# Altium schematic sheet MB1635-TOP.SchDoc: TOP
size A3; Date: Not used; ApprovedBy: Not used; CheckedBy: Not used; Author: Not used; CompanyName: STMicroelectronics; DrawnBy: Not used; Engineer: Not used; Organization: Not used; Address1: Not used; Address2: Not used; Address3: Not used; Address4: Not used; DocumentNumber: 2; Revision: Not used; SheetNumber: 2; SheetTotal: 17
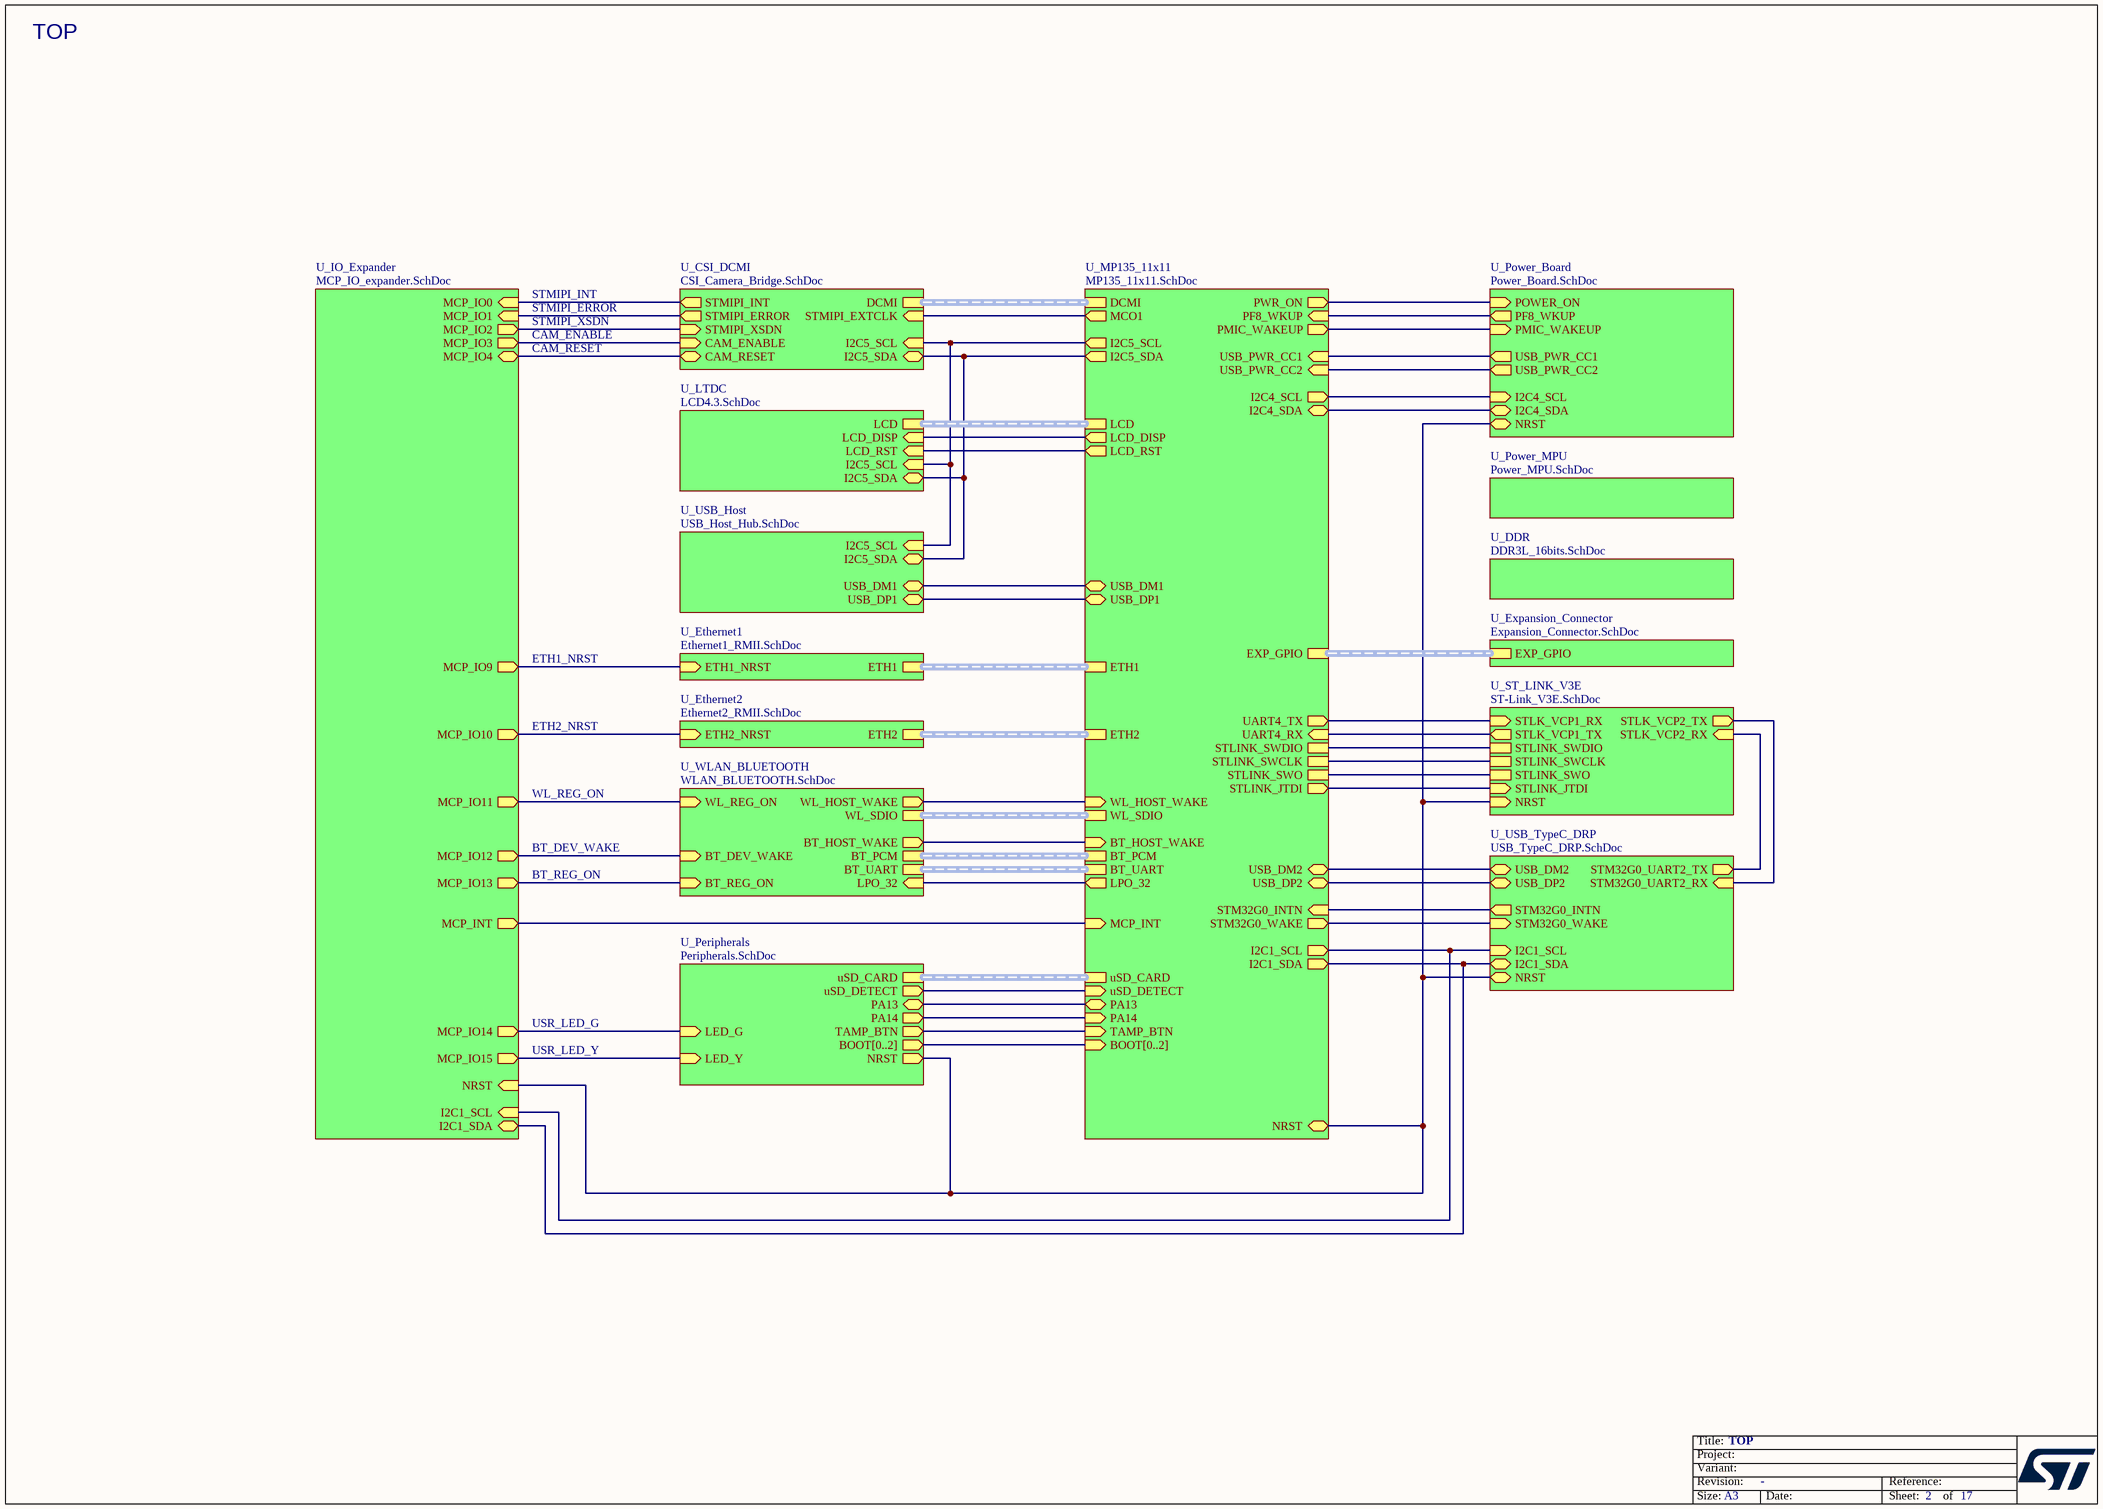
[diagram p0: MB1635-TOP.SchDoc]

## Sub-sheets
U_CSI_DCMI = CSI_Camera_Bridge.SchDoc: DCMI (harness DCMI), I2C5_SCL (in), I2C5_SDA (bidir), STMIPI_EXTCLK (in), STMIPI_ERROR (out), STMIPI_INT (out), CAM_ENABLE (in), CAM_RESET (bidir), STMIPI_XSDN (in)
U_DDR = DDR3L_16bits.SchDoc: no entries
U_Ethernet1 = Ethernet1_RMII.SchDoc: ETH1 (harness ETH1), ETH1_NRST (in)
U_Ethernet2 = Ethernet2_RMII.SchDoc: ETH2 (harness ETH2), ETH2_NRST (in)
U_Expansion_Connector = Expansion_Connector.SchDoc: EXP_GPIO (harness EXP_GPIO)
U_IO_Expander = MCP_IO_expander.SchDoc: MCP_IO1 (in), MCP_IO0 (in), MCP_IO9 (out), MCP_IO10 (out), MCP_IO11 (out), MCP_IO12 (out), MCP_IO13 (out), MCP_IO14 (out), MCP_IO15 (out), I2C1_SCL (in), I2C1_SDA (bidir), MCP_INT (out), NRST (in), MCP_IO3 (out), MCP_IO4 (bidir), MCP_IO2 (out)
U_LTDC = LCD4.3.SchDoc: LCD (harness LCD), I2C5_SCL (in), I2C5_SDA (bidir), LCD_DISP (in), LCD_RST (in)
U_MP135_11x11 = MP135_11x11.SchDoc: uSD_CARD (harness uSD_CARD), PMIC_WAKEUP (out), PF8_WKUP (in), NRST (bidir), PWR_ON (out), ETH2 (harness ETH2), ETH1 (harness ETH1), I2C1_SCL (out), I2C1_SDA (out), I2C4_SCL (out), I2C4_SDA (bidir), UART4_TX (out), UART4_RX (in), LCD (harness LCD), WL_SDIO (harness WL_SDIO), BOOT[0..2] (in), WL_HOST_WAKE (in), BT_HOST_WAKE (in), LPO_32 (out), BT_PCM (harness BT_PCM), BT_UART (harness BT_UART), DCMI (harness DCMI), EXP_GPIO (harness EXP_GPIO), USB_DM1 (bidir), USB_DM2 (bidir), USB_DP1 (bidir), USB_DP2 (bidir), MCO1 (out), USB_PWR_CC1 (in), USB_PWR_CC2 (in), STLINK_SWDIO, STLINK_SWCLK, STLINK_SWO, PA14 (in), PA13 (bidir), STM32G0_INTN (in), STM32G0_WAKE (out), MCP_INT (in), TAMP_BTN (in), uSD_DETECT (in), LCD_DISP (out), LCD_RST (out), I2C5_SCL (out), I2C5_SDA (out), STLINK_JTDI (out)
U_Peripherals = Peripherals.SchDoc: NRST (out), BOOT[0..2] (out), uSD_CARD (harness uSD_CARD), PA13 (bidir), PA14 (out), LED_Y (in), LED_G (in), uSD_DETECT (out), TAMP_BTN (out)
U_Power_Board = Power_Board.SchDoc: I2C4_SDA (bidir), I2C4_SCL (in), PF8_WKUP (out), NRST (bidir), POWER_ON (in), USB_PWR_CC1 (out), USB_PWR_CC2 (out), PMIC_WAKEUP (in)
U_Power_MPU = Power_MPU.SchDoc: no entries
U_ST_LINK_V3E = ST-Link_V3E.SchDoc: STLINK_SWDIO, STLINK_SWCLK, STLINK_SWO, STLK_VCP1_RX (in), STLK_VCP1_TX (out), STLK_VCP2_TX (out), STLK_VCP2_RX (in), NRST (in), STLINK_JTDI (in)
U_USB_Host = USB_Host_Hub.SchDoc: USB_DM1 (bidir), USB_DP1 (bidir), I2C5_SDA (bidir), I2C5_SCL (in)
U_USB_TypeC_DRP = USB_TypeC_DRP.SchDoc: USB_DM2 (bidir), USB_DP2 (bidir), I2C1_SCL (in), I2C1_SDA (bidir), STM32G0_INTN (out), STM32G0_WAKE (in), STM32G0_UART2_TX (out), STM32G0_UART2_RX (in), NRST (bidir)
U_WLAN_BLUETOOTH = WLAN_BLUETOOTH.SchDoc: BT_PCM (harness BT_PCM), BT_UART (harness BT_UART), WL_SDIO (harness WL_SDIO), BT_REG_ON (in), BT_HOST_WAKE (out), BT_DEV_WAKE (in), WL_REG_ON (in), WL_HOST_WAKE (out), LPO_32 (in)

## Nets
(unnamed): sheet U_Ethernet1/ETH1_NRST, sheet U_IO_Expander/MCP_IO9
(unnamed): sheet U_Ethernet2/ETH2_NRST, sheet U_IO_Expander/MCP_IO10  [a separate net that carries the same name]
(unnamed): sheet U_Power_Board/I2C4_SDA, sheet U_MP135_11x11/I2C4_SDA  [a separate net that carries the same name]
(unnamed): sheet U_Power_Board/I2C4_SCL, sheet U_MP135_11x11/I2C4_SCL  [a separate net that carries the same name]
(unnamed): sheet U_Power_Board/PF8_WKUP, sheet U_MP135_11x11/PF8_WKUP  [a separate net that carries the same name]
(unnamed): sheet U_Power_Board/NRST, sheet U_ST_LINK_V3E/NRST, sheet U_Peripherals/NRST, sheet U_MP135_11x11/NRST, sheet U_IO_Expander/NRST, sheet U_USB_TypeC_DRP/NRST  [a separate net that carries the same name]
(unnamed): sheet U_Power_Board/POWER_ON, sheet U_MP135_11x11/PWR_ON  [a separate net that carries the same name]
(unnamed): sheet U_Power_Board/USB_PWR_CC1, sheet U_MP135_11x11/USB_PWR_CC1  [a separate net that carries the same name]
(unnamed): sheet U_Power_Board/USB_PWR_CC2, sheet U_MP135_11x11/USB_PWR_CC2  [a separate net that carries the same name]
(unnamed): sheet U_Power_Board/PMIC_WAKEUP, sheet U_MP135_11x11/PMIC_WAKEUP  [a separate net that carries the same name]
(unnamed): sheet U_ST_LINK_V3E/STLINK_SWDIO, sheet U_MP135_11x11/STLINK_SWDIO  [a separate net that carries the same name]
(unnamed): sheet U_ST_LINK_V3E/STLINK_SWCLK, sheet U_MP135_11x11/STLINK_SWCLK  [a separate net that carries the same name]
(unnamed): sheet U_ST_LINK_V3E/STLINK_SWO, sheet U_MP135_11x11/STLINK_SWO  [a separate net that carries the same name]
(unnamed): sheet U_ST_LINK_V3E/STLK_VCP1_RX, sheet U_MP135_11x11/UART4_TX  [a separate net that carries the same name]
(unnamed): sheet U_ST_LINK_V3E/STLK_VCP1_TX, sheet U_MP135_11x11/UART4_RX  [a separate net that carries the same name]
(unnamed): sheet U_ST_LINK_V3E/STLK_VCP2_TX, sheet U_USB_TypeC_DRP/STM32G0_UART2_RX  [a separate net that carries the same name]
(unnamed): sheet U_ST_LINK_V3E/STLK_VCP2_RX, sheet U_USB_TypeC_DRP/STM32G0_UART2_TX  [a separate net that carries the same name]
(unnamed): sheet U_ST_LINK_V3E/STLINK_JTDI, sheet U_MP135_11x11/STLINK_JTDI  [a separate net that carries the same name]
(unnamed): sheet U_WLAN_BLUETOOTH/BT_REG_ON, sheet U_IO_Expander/MCP_IO13  [a separate net that carries the same name]
(unnamed): sheet U_WLAN_BLUETOOTH/BT_HOST_WAKE, sheet U_MP135_11x11/BT_HOST_WAKE  [a separate net that carries the same name]
(unnamed): sheet U_WLAN_BLUETOOTH/BT_DEV_WAKE, sheet U_IO_Expander/MCP_IO12  [a separate net that carries the same name]
(unnamed): sheet U_WLAN_BLUETOOTH/WL_REG_ON, sheet U_IO_Expander/MCP_IO11  [a separate net that carries the same name]
(unnamed): sheet U_WLAN_BLUETOOTH/WL_HOST_WAKE, sheet U_MP135_11x11/WL_HOST_WAKE  [a separate net that carries the same name]
(unnamed): sheet U_WLAN_BLUETOOTH/LPO_32, sheet U_MP135_11x11/LPO_32  [a separate net that carries the same name]
(unnamed): sheet U_Peripherals/PA13, sheet U_MP135_11x11/PA13  [a separate net that carries the same name]
(unnamed): sheet U_Peripherals/PA14, sheet U_MP135_11x11/PA14  [a separate net that carries the same name]
(unnamed): sheet U_Peripherals/LED_Y, sheet U_IO_Expander/MCP_IO15  [a separate net that carries the same name]
(unnamed): sheet U_Peripherals/LED_G, sheet U_IO_Expander/MCP_IO14  [a separate net that carries the same name]
(unnamed): sheet U_Peripherals/uSD_DETECT, sheet U_MP135_11x11/uSD_DETECT  [a separate net that carries the same name]
(unnamed): sheet U_Peripherals/TAMP_BTN, sheet U_MP135_11x11/TAMP_BTN  [a separate net that carries the same name]
(unnamed): sheet U_MP135_11x11/I2C1_SCL, sheet U_IO_Expander/I2C1_SCL, sheet U_USB_TypeC_DRP/I2C1_SCL  [a separate net that carries the same name]
(unnamed): sheet U_MP135_11x11/I2C1_SDA, sheet U_IO_Expander/I2C1_SDA, sheet U_USB_TypeC_DRP/I2C1_SDA  [a separate net that carries the same name]
(unnamed): sheet U_MP135_11x11/USB_DM1, sheet U_USB_Host/USB_DM1  [a separate net that carries the same name]
(unnamed): sheet U_MP135_11x11/USB_DM2, sheet U_USB_TypeC_DRP/USB_DM2  [a separate net that carries the same name]
(unnamed): sheet U_MP135_11x11/USB_DP1, sheet U_USB_Host/USB_DP1  [a separate net that carries the same name]
(unnamed): sheet U_MP135_11x11/USB_DP2, sheet U_USB_TypeC_DRP/USB_DP2  [a separate net that carries the same name]
(unnamed): sheet U_MP135_11x11/MCO1, sheet U_CSI_DCMI/STMIPI_EXTCLK  [a separate net that carries the same name]
(unnamed): sheet U_MP135_11x11/STM32G0_INTN, sheet U_USB_TypeC_DRP/STM32G0_INTN  [a separate net that carries the same name]
(unnamed): sheet U_MP135_11x11/STM32G0_WAKE, sheet U_USB_TypeC_DRP/STM32G0_WAKE  [a separate net that carries the same name]
(unnamed): sheet U_MP135_11x11/MCP_INT, sheet U_IO_Expander/MCP_INT  [a separate net that carries the same name]
(unnamed): sheet U_MP135_11x11/LCD_DISP, sheet U_LTDC/LCD_DISP  [a separate net that carries the same name]
(unnamed): sheet U_MP135_11x11/LCD_RST, sheet U_LTDC/LCD_RST  [a separate net that carries the same name]
(unnamed): sheet U_MP135_11x11/I2C5_SCL, sheet U_LTDC/I2C5_SCL, sheet U_USB_Host/I2C5_SCL, sheet U_CSI_DCMI/I2C5_SCL  [a separate net that carries the same name]
(unnamed): sheet U_MP135_11x11/I2C5_SDA, sheet U_LTDC/I2C5_SDA, sheet U_USB_Host/I2C5_SDA, sheet U_CSI_DCMI/I2C5_SDA  [a separate net that carries the same name]
(unnamed): sheet U_IO_Expander/MCP_IO1, sheet U_CSI_DCMI/STMIPI_ERROR  [a separate net that carries the same name]
(unnamed): sheet U_IO_Expander/MCP_IO0, sheet U_CSI_DCMI/STMIPI_INT  [a separate net that carries the same name]
(unnamed): sheet U_IO_Expander/MCP_IO3, sheet U_CSI_DCMI/CAM_ENABLE  [a separate net that carries the same name]
(unnamed): sheet U_IO_Expander/MCP_IO4, sheet U_CSI_DCMI/CAM_RESET  [a separate net that carries the same name]
(unnamed): sheet U_IO_Expander/MCP_IO2, sheet U_CSI_DCMI/STMIPI_XSDN  [a separate net that carries the same name]

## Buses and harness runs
bus sheet U_MP135_11x11/BOOT[0..2] = sheet U_Peripherals/BOOT[0..2]
harness sheet U_CSI_DCMI/DCMI = sheet U_MP135_11x11/DCMI
harness sheet U_Ethernet1/ETH1 = sheet U_MP135_11x11/ETH1
harness sheet U_Ethernet2/ETH2 = sheet U_MP135_11x11/ETH2
harness sheet U_Expansion_Connector/EXP_GPIO = sheet U_MP135_11x11/EXP_GPIO
harness sheet U_LTDC/LCD = sheet U_MP135_11x11/LCD
harness sheet U_MP135_11x11/BT_PCM = sheet U_WLAN_BLUETOOTH/BT_PCM
harness sheet U_MP135_11x11/BT_UART = sheet U_WLAN_BLUETOOTH/BT_UART
harness sheet U_MP135_11x11/uSD_CARD = sheet U_Peripherals/uSD_CARD
harness sheet U_MP135_11x11/WL_SDIO = sheet U_WLAN_BLUETOOTH/WL_SDIO

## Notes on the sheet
- TOP
- STMIPI_INT
- STMIPI_ERROR
- CAM_RESET
- CAM_ENABLE
- STMIPI_XSDN
- ETH1_NRST
- ETH2_NRST
- BT_DEV_WAKE
- WL_REG_ON
- BT_REG_ON
- USR_LED_Y
- USR_LED_G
